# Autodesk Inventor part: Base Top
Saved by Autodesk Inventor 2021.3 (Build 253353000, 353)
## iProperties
Created: 2022-04
Part Number: Base Top
Material: Generic
Document SubType Name: Modeling
Designer: Administrator
Density: 1 g/cm^3
Appearance: Default
Title: Base Top v30
Author: Administrator
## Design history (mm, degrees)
feature "Body2"
body "Solid1"
